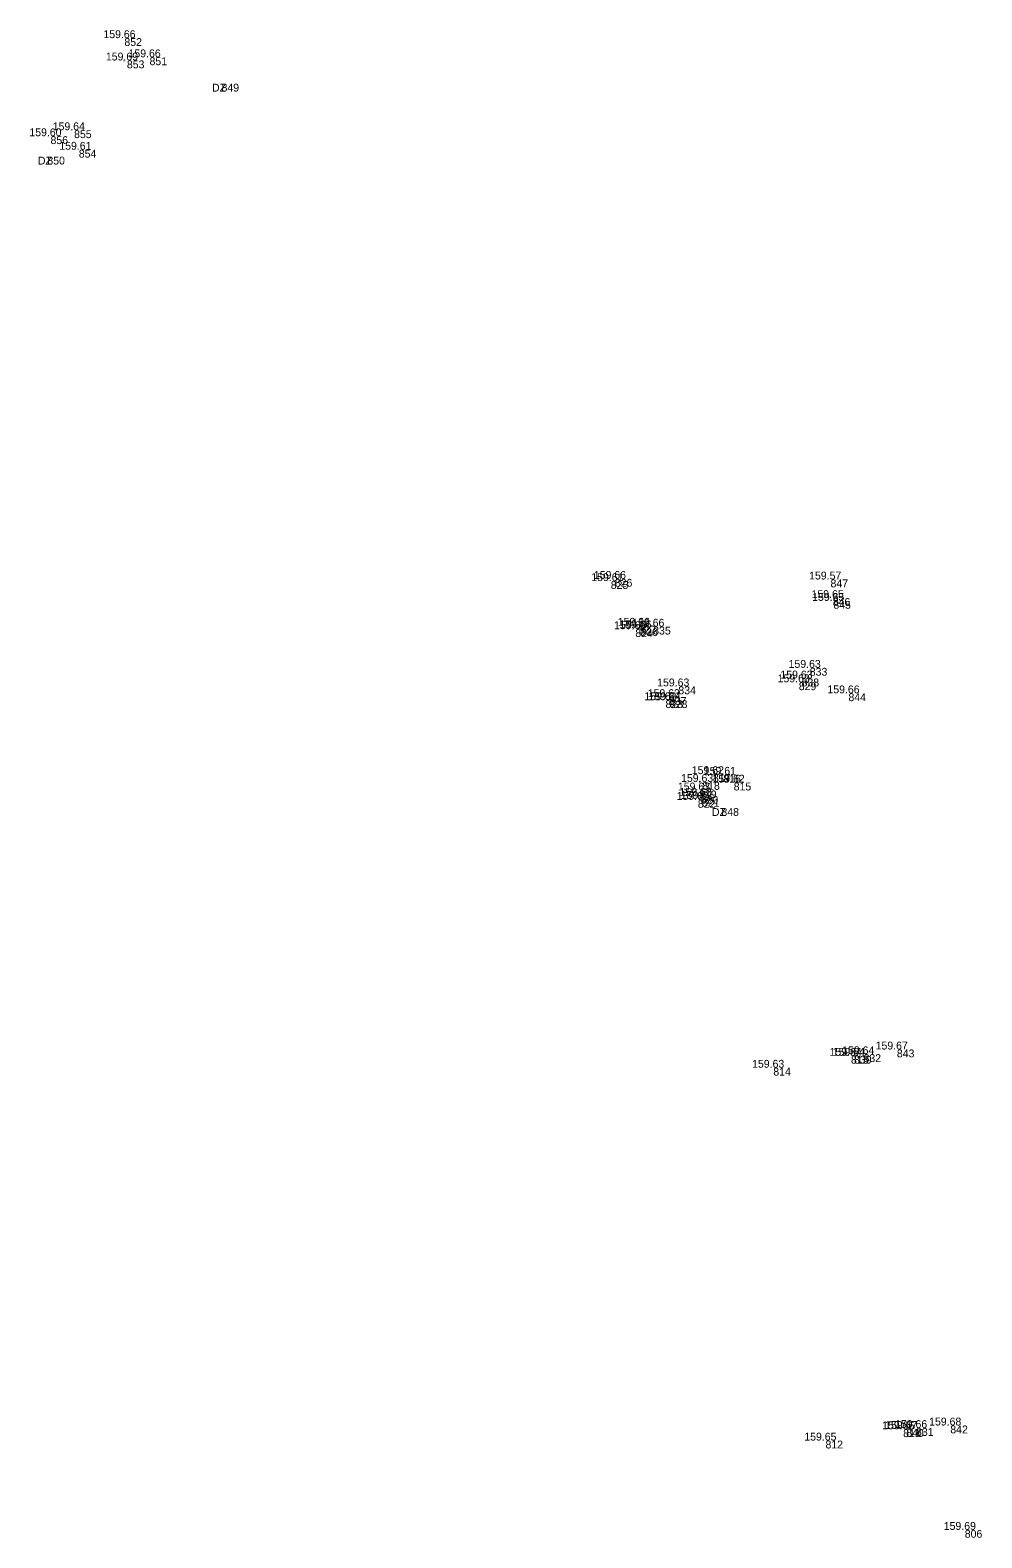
# Model space of a CAD drawing. Extents: x -583198 to -582878, y -1211024 to -1210637.
# Drawn here: x -582909.11 to -582878.84, y -1210685.06 to -1210637.11 of the extents above; entities that cross this region are included whole.
import ezdxf

# ---------------------------------------------------------------- set-up
doc = ezdxf.new("R2010")
doc.units = 0
for name, color, linetype in [('1   Kódy', 7, 'Continuous'), ('4   Body podrobné', 7, 'Continuous'), ('5   Body podrobné - čísla', 7, 'Continuous'), ('6   Body podrobné - výšky', 7, 'Continuous')]:
    doc.layers.add(name, color=color, linetype=linetype)

msp = doc.modelspace()

# ---------------------------------------------------------------- linework, layer by layer
at = {"layer": '4   Body podrobné'}
for p, q in [((-582906.21, -1210637.36), (-582906.209, -1210637.36)), ((-582906.13, -1210638.07), (-582906.129, -1210638.07)), ((-582905.41, -1210637.97), (-582905.409, -1210637.97)), ((-582903.12, -1210638.81), (-582903.119, -1210638.81)), ((-582908.56, -1210640.48), (-582908.559, -1210640.48)), ((-582907.81, -1210640.29), (-582907.809, -1210640.29)), ((-582907.66, -1210640.91), (-582907.659, -1210640.91)), ((-582908.66, -1210641.13), (-582908.659, -1210641.13)), ((-582890.74, -1210654.63), (-582890.739, -1210654.63)), ((-582890.61, -1210654.56), (-582890.609, -1210654.56)), ((-582883.75, -1210654.58), (-582883.749, -1210654.58)), ((-582883.68, -1210655.17), (-582883.679, -1210655.17)), ((-582883.66, -1210655.26), (-582883.659, -1210655.26)), ((-582889.96, -1210656.16), (-582889.959, -1210656.16)), ((-582889.85, -1210656.05), (-582889.849, -1210656.05)), ((-582889.8, -1210656.13), (-582889.799, -1210656.13)), ((-582889.39, -1210656.08), (-582889.389, -1210656.08)), ((-582884.41, -1210657.39), (-582884.409, -1210657.39)), ((-582884.76, -1210657.85), (-582884.759, -1210657.85)), ((-582884.67, -1210657.73), (-582884.669, -1210657.73)), ((-582888.89, -1210658.32), (-582888.889, -1210658.32)), ((-582888.59, -1210657.98), (-582888.589, -1210657.98)), ((-582883.18, -1210658.2), (-582883.179, -1210658.2)), ((-582889, -1210658.42), (-582888.999, -1210658.42)), ((-582888.86, -1210658.42), (-582888.859, -1210658.42)), ((-582887.49, -1210660.77), (-582887.489, -1210660.77)), ((-582887.83, -1210661.02), (-582887.829, -1210661.02)), ((-582887.16, -1210660.79), (-582887.159, -1210660.79)), ((-582886.83, -1210661.04), (-582886.829, -1210661.04)), ((-582887.97, -1210661.59), (-582887.969, -1210661.59)), ((-582887.93, -1210661.29), (-582887.929, -1210661.29)), ((-582887.88, -1210661.46), (-582887.879, -1210661.46)), ((-582887.84, -1210661.56), (-582887.839, -1210661.56)), ((-582887.22, -1210661.85), (-582887.219, -1210661.85)), ((-582883.1, -1210669.73), (-582883.099, -1210669.73)), ((-582883, -1210669.73), (-582882.999, -1210669.73)), ((-582882.7, -1210669.68), (-582882.699, -1210669.68)), ((-582881.64, -1210669.53), (-582881.639, -1210669.53)), ((-582885.57, -1210670.11), (-582885.569, -1210670.11)), ((-582881.44, -1210681.61), (-582881.439, -1210681.61)), ((-582881.34, -1210681.6), (-582881.339, -1210681.6)), ((-582881.03, -1210681.57), (-582881.029, -1210681.57)), ((-582879.94, -1210681.49), (-582879.939, -1210681.49)), ((-582883.91, -1210681.97), (-582883.909, -1210681.97)), ((-582879.48, -1210684.81), (-582879.479, -1210684.81))]:
    msp.add_line(p, q, dxfattribs=at)

# ---------------------------------------------------------------- texts
at = {"layer": '1   Kódy'}
for p in [(-582903.329, -1210639.06), (-582908.869, -1210641.38), (-582887.429, -1210662.1)]:
    msp.add_text('DZ', height=0.25, dxfattribs=at).set_placement(p)
at = {"layer": '5   Body podrobné - čísla'}
for s, p in [(' 852', (-582906.21, -1210637.61)), (' 853', (-582906.13, -1210638.32)), (' 851', (-582905.41, -1210638.22)), (' 849', (-582903.12, -1210639.06)), (' 856', (-582908.56, -1210640.73)), (' 855', (-582907.81, -1210640.54)), (' 854', (-582907.66, -1210641.16)), (' 850', (-582908.66, -1210641.38)), (' 825', (-582890.74, -1210654.88)), (' 826', (-582890.61, -1210654.81)), (' 847', (-582883.75, -1210654.83)), (' 846', (-582883.68, -1210655.42)), (' 845', (-582883.66, -1210655.51)), (' 824', (-582889.96, -1210656.41)), (' 827', (-582889.85, -1210656.3)), (' 836', (-582889.8, -1210656.38)), (' 835', (-582889.39, -1210656.33)), (' 833', (-582884.41, -1210657.64)), (' 829', (-582884.76, -1210658.1)), (' 838', (-582884.67, -1210657.98)), (' 837', (-582888.89, -1210658.57)), (' 834', (-582888.59, -1210658.23)), (' 844', (-582883.18, -1210658.45)), (' 823', (-582889, -1210658.67)), (' 828', (-582888.86, -1210658.67)), (' 817', (-582887.49, -1210661.02)), (' 818', (-582887.83, -1210661.27)), (' 816', (-582887.16, -1210661.04)), (' 815', (-582886.83, -1210661.29)), (' 822', (-582887.97, -1210661.84)), (' 819', (-582887.93, -1210661.54)), (' 820', (-582887.88, -1210661.71)), (' 821', (-582887.84, -1210661.81)), (' 848', (-582887.22, -1210662.1)), (' 813', (-582883.1, -1210669.98)), (' 839', (-582883, -1210669.98)), (' 832', (-582882.7, -1210669.93)), (' 843', (-582881.64, -1210669.78)), (' 814', (-582885.57, -1210670.36)), (' 811', (-582881.44, -1210681.86)), (' 840', (-582881.34, -1210681.85)), (' 831', (-582881.03, -1210681.82)), (' 842', (-582879.94, -1210681.74)), (' 812', (-582883.91, -1210682.22)), (' 806', (-582879.48, -1210685.06))]:
    msp.add_text(s, height=0.25, dxfattribs=at).set_placement(p)
at = {"layer": '6   Body podrobné - výšky'}
for s, p in [('159.66', (-582906.785, -1210637.36)), ('159.66', (-582905.985, -1210637.97)), ('159.69', (-582906.705, -1210638.07)), ('159.64', (-582908.397, -1210640.29)), ('159.60', (-582909.14, -1210640.48)), ('159.61', (-582908.187, -1210640.91)), ('159.61', (-582891.267, -1210654.63)), ('159.66', (-582891.185, -1210654.56)), ('159.57', (-582884.338, -1210654.58)), ('159.65', (-582884.261, -1210655.17)), ('159.65', (-582884.241, -1210655.26)), ('159.63', (-582890.541, -1210656.16)), ('159.66', (-582890.425, -1210656.05)), ('159.66', (-582890.375, -1210656.13)), ('159.66', (-582889.965, -1210656.08)), ('159.63', (-582884.991, -1210657.39)), ('159.63', (-582889.171, -1210657.98)), ('159.63', (-582885.341, -1210657.85)), ('159.63', (-582885.251, -1210657.73)), ('159.62', (-582889.581, -1210658.42)), ('159.63', (-582889.471, -1210658.32)), ('159.64', (-582889.447, -1210658.42)), ('159.66', (-582883.755, -1210658.2)), ('159.63', (-582888.411, -1210661.02)), ('159.62', (-582888.071, -1210660.77)), ('159.61', (-582887.687, -1210660.79)), ('159.63', (-582888.511, -1210661.29)), ('159.63', (-582888.461, -1210661.46)), ('159.62', (-582887.411, -1210661.04)), ('159.62', (-582888.551, -1210661.59)), ('159.62', (-582888.421, -1210661.56)), ('159.67', (-582882.222, -1210669.53)), ('159.63', (-582886.151, -1210670.11)), ('159.64', (-582883.687, -1210669.73)), ('159.64', (-582883.587, -1210669.73)), ('159.64', (-582883.287, -1210669.68)), ('159.66', (-582882.015, -1210681.61)), ('159.67', (-582881.922, -1210681.6)), ('159.66', (-582881.605, -1210681.57)), ('159.68', (-582880.521, -1210681.49)), ('159.65', (-582884.491, -1210681.97)), ('159.69', (-582880.055, -1210684.81))]:
    msp.add_text(s, height=0.25, dxfattribs=at).set_placement(p)

doc.saveas('drawing.dxf')
